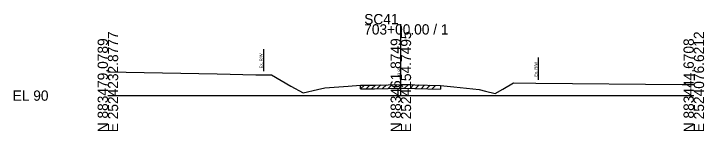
# Model space of a CAD drawing. Extents: x -26 to 183, y -10 to 24021.
# Drawn here: x -25.7 to 162.8, y 23490.3 to 23522.3 of the extents above; entities that cross this region are included whole.
import ezdxf

# ---------------------------------------------------------------- set-up
doc = ezdxf.new("R2010")
doc.units = 0
for name, color, linetype in [('RD_GPK_XS_Cell', 7, 'Continuous'), ('RD_XS_ExGround', 7, 'Continuous'), ('RD_XS_ExPaveRet', 7, 'Continuous'), ('RD_XS_ExRW', 7, 'Continuous'), ('RD_XS_TX_Elev_EX', 7, 'Continuous')]:
    doc.layers.add(name, color=color, linetype=linetype)

msp = doc.modelspace()

# ---------------------------------------------------------------- linework, layer by layer
at = {"layer": 'RD_GPK_XS_Cell'}
for p, q in [((80, 23500), (80, 23519.44)), ((0, 23500), (80, 23500)), ((80, 23500), (160, 23500))]:
    msp.add_line(p, q, dxfattribs=at)
at = {"layer": 'RD_XS_ExGround'}
for p, q in [((0, 23506.48), (29.86, 23505.91)), ((29.86, 23505.91), (40.39, 23505.68)), ((40.39, 23505.68), (44.65, 23505.62)), ((44.65, 23505.62), (49.93, 23502.6)), ((49.93, 23502.6), (53.32, 23500.73)), ((59.23, 23502.08), (65.59, 23502.53)), ((65.59, 23502.53), (69.02, 23502.8)), ((69.02, 23502.8), (72.78, 23502.88)), ((72.78, 23502.88), (80.25, 23503.01)), ((80.25, 23503.01), (83.85, 23502.92)), ((83.85, 23502.92), (90.82, 23502.75)), ((90.82, 23502.75), (94.47, 23502.38)), ((107.82, 23501.76), (110.79, 23503.44)), ((110.79, 23503.44), (116.86, 23503.35)), ((116.86, 23503.35), (156.83, 23503)), ((156.83, 23503), (160, 23503.01)), ((53.32, 23500.73), (57.24, 23501.62)), ((57.24, 23501.62), (59.23, 23502.08)), ((94.47, 23502.38), (101.42, 23501.68)), ((101.42, 23501.68), (103.09, 23501.24)), ((103.09, 23501.24), (105.77, 23500.58)), ((105.77, 23500.58), (107.82, 23501.76))]:
    msp.add_line(p, q, dxfattribs=at)
at = {"layer": 'RD_XS_ExPaveRet'}
for p, q in [((69.02, 23501.8), (70.05, 23502.82)), ((69.02, 23501.8), (69.02, 23502.8)), ((70.52, 23501.83), (71.55, 23502.85)), ((72.02, 23501.86), (73.04, 23502.88)), ((73.52, 23501.89), (74.54, 23502.91)), ((75.02, 23501.92), (76.04, 23502.94)), ((76.52, 23501.95), (77.54, 23502.96)), ((78.02, 23501.97), (79.04, 23502.99)), ((79.52, 23502), (80.53, 23503)), ((81.02, 23501.99), (82, 23502.96)), ((82.52, 23501.95), (83.5, 23502.93)), ((84.02, 23501.91), (85, 23502.89)), ((85.52, 23501.88), (86.5, 23502.85)), ((87.02, 23501.84), (88, 23502.81)), ((88.52, 23501.8), (89.5, 23502.78)), ((90.82, 23502.75), (90.82, 23501.75)), ((69.02, 23501.8), (72.78, 23501.88)), ((72.78, 23501.88), (80.25, 23502.01)), ((80.25, 23502.01), (83.85, 23501.92)), ((83.85, 23501.92), (90.82, 23501.75))]:
    msp.add_line(p, q, dxfattribs=at)
at = {"layer": 'RD_XS_ExRW'}
for p, q in [((42.5, 23512.65), (42.5, 23506.65)), ((117.5, 23510.34), (117.5, 23504.34))]:
    msp.add_line(p, q, dxfattribs=at)

# ---------------------------------------------------------------- texts
at = {"layer": 'RD_GPK_XS_Cell'}
for s, p in [('SC41', (70, 23519.44)), ('703+00.00 / 1', (70, 23516.64)), ('EL 90', (-26, 23498.6))]:
    msp.add_text(s, height=2.8, dxfattribs=at).set_placement(p)
for s, p in [('E 2524232.8777', (2.8, 23490)), ('E 2524154.7495', (82.8, 23490)), ('E 2524076.6212', (162.8, 23490)), ('N 883479.0789', (0, 23490)), ('N 883461.8749', (80, 23490)), ('N 883444.6708', (160, 23490))]:
    msp.add_text(s, height=2.8, rotation=90, dxfattribs=at).set_placement(p)
at = {"layer": 'RD_XS_ExRW'}
for p in [(42.25, 23507.44), (117.25, 23505.13)]:
    msp.add_text('Ex. R/W ', height=0.8, rotation=90, dxfattribs=at).set_placement(p)
at = {"layer": 'RD_XS_TX_Elev_EX'}
msp.add_text('93.01', height=0.8, rotation=90, dxfattribs=at).set_placement((79.9, 23505.01))

doc.saveas('drawing.dxf')
